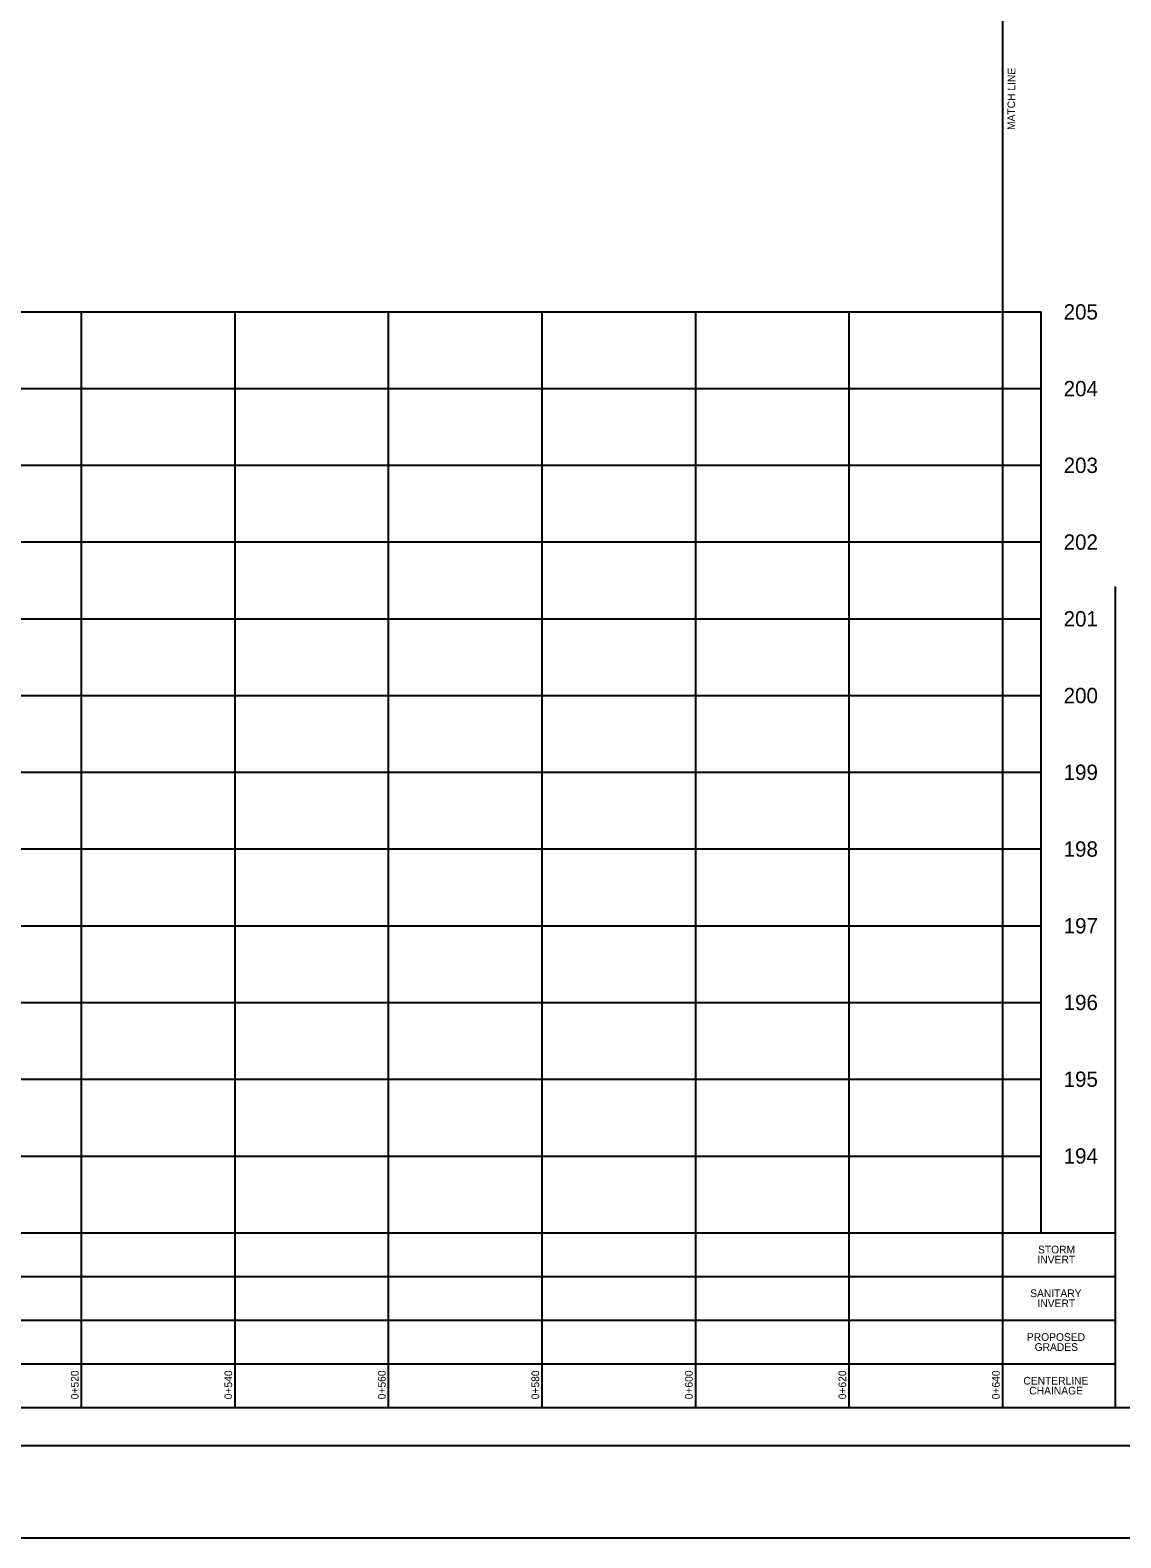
# Model space of a CAD drawing. Extents: x 595568 to 603709, y 4837996 to 4846716.
# Drawn here: x 603142.9 to 603285, y 4846340.6 to 4846537.1 of the extents above; entities that cross this region are included whole.
import ezdxf

# ---------------------------------------------------------------- set-up
doc = ezdxf.new("R2010")
doc.units = 0
for name, color, linetype in [('-PRINT FULLSIZE', 7, 'Continuous'), ('-PRINT HALFSIZE', 7, 'Continuous'), ('ENG_BORDER', 7, 'Continuous'), ('ENG_DIMENSIONS', 7, 'Continuous'), ('ENG_GRID', 7, 'Continuous'), ('ENG_GRIDBORDER', 7, 'Continuous'), ('ENG_TX_DIMENSIONS', 7, 'Continuous'), ('ENG_TX_GRID', 7, 'Continuous')]:
    doc.layers.add(name, color=color, linetype=linetype)

msp = doc.modelspace()

# ---------------------------------------------------------------- linework, layer by layer
at = {"layer": '-PRINT FULLSIZE'}
msp.add_lwpolyline([(602930, 4846340.65), (603377.03, 4846340.65), (603377.03, 4846645.65), (602930, 4846645.65)], close=True, dxfattribs=at)
at = {"layer": '-PRINT HALFSIZE'}
msp.add_lwpolyline([(602959.8, 4846631.64), (603368.72, 4846631.64), (603368.72, 4846352.64), (602959.8, 4846352.64)], close=True, dxfattribs=at)
at = {"layer": 'ENG_BORDER'}
msp.add_line((603284.31, 4846357.64), (603284.31, 4846464.61), dxfattribs=at)
msp.add_lwpolyline([(602975.52, 4846357.64), (603363.72, 4846357.64), (603363.72, 4846626.64), (602975.52, 4846626.64)], close=True, dxfattribs=at)
at = {"layer": 'ENG_DIMENSIONS'}
msp.add_line((603269.61, 4846500.41), (603269.61, 4846626.64), dxfattribs=at)
at = {"layer": 'ENG_GRID'}
for p, q in [((602984.61, 4846500.41), (603274.61, 4846500.41)), ((603149.61, 4846380.41), (603149.61, 4846500.41)), ((603169.61, 4846380.41), (603169.61, 4846500.41)), ((603189.61, 4846380.41), (603189.61, 4846500.41)), ((603209.61, 4846380.41), (603209.61, 4846500.41)), ((603229.61, 4846380.41), (603229.61, 4846500.41)), ((603249.61, 4846380.41), (603249.61, 4846500.41)), ((603269.61, 4846380.41), (603269.61, 4846500.41)), ((602984.61, 4846490.41), (603274.61, 4846490.41)), ((602984.61, 4846480.41), (603274.61, 4846480.41)), ((602984.61, 4846470.41), (603274.61, 4846470.41)), ((602984.61, 4846460.41), (603274.61, 4846460.41)), ((602984.61, 4846450.41), (603274.61, 4846450.41)), ((602984.61, 4846440.41), (603274.61, 4846440.41)), ((602984.61, 4846430.41), (603274.61, 4846430.41)), ((602984.61, 4846420.41), (603274.61, 4846420.41)), ((602984.61, 4846410.41), (603274.61, 4846410.41)), ((602984.61, 4846400.41), (603274.61, 4846400.41)), ((602984.61, 4846390.39), (603274.61, 4846390.39)), ((603149.61, 4846357.64), (603149.61, 4846380.41)), ((603169.61, 4846357.64), (603169.61, 4846380.41)), ((603189.61, 4846357.64), (603189.61, 4846380.41)), ((603209.61, 4846357.64), (603209.61, 4846380.41)), ((603229.61, 4846357.64), (603229.61, 4846380.41)), ((603249.61, 4846357.64), (603249.61, 4846380.41)), ((603269.61, 4846357.64), (603269.61, 4846380.41)), ((602975.52, 4846374.71), (603284.31, 4846374.71)), ((602975.52, 4846369.01), (603284.31, 4846369.01)), ((602975.52, 4846363.31), (603284.31, 4846363.31))]:
    msp.add_line(p, q, dxfattribs=at)
at = {"layer": 'ENG_GRIDBORDER'}
for p, q in [((603274.61, 4846380.41), (603274.61, 4846500.41)), ((602975.52, 4846380.41), (603284.31, 4846380.41))]:
    msp.add_line(p, q, dxfattribs=at)

# ---------------------------------------------------------------- texts
at = {"layer": 'ENG_TX_DIMENSIONS'}
msp.add_text('MATCH LINE', height=1, rotation=89.6422, dxfattribs=at).set_placement((603271.21, 4846524.09))
at = {"layer": 'ENG_TX_GRID'}
for s, height, rotation, p in [('205', 2, 360, (603277.55, 4846499.39)), ('204', 2, 360, (603277.55, 4846489.39)), ('203', 2, 360, (603277.55, 4846479.4)), ('202', 2, 360, (603277.55, 4846469.4)), ('201', 2, 360, (603277.55, 4846459.4)), ('200', 2, 360, (603277.55, 4846449.4)), ('199', 2, 360, (603277.55, 4846439.4)), ('198', 2, 360, (603277.55, 4846429.4)), ('197', 2, 360, (603277.55, 4846419.4)), ('196', 2, 360, (603277.55, 4846409.41)), ('195', 2, 360, (603277.55, 4846399.41)), ('194', 2, 360, (603277.55, 4846389.41)), ('STORM', 1, 360, (603274.21, 4846377.71)), ('INVERT', 1, 360, (603274.14, 4846376.41)), ('SANITARY', 1, 360, (603273.19, 4846372.01)), ('INVERT', 1, 360, (603274.14, 4846370.71)), ('PROPOSED', 1, 360, (603272.76, 4846366.31)), ('GRADES', 1, 360, (603273.77, 4846365.01)), ('0+520', 1, 90, (603149.22, 4846358.7)), ('0+540', 1, 90, (603169.22, 4846358.7)), ('0+560', 1, 90, (603189.22, 4846358.7)), ('0+580', 1, 90, (603209.22, 4846358.7)), ('0+600', 1, 90, (603229.22, 4846358.7)), ('0+620', 1, 90, (603249.22, 4846358.7)), ('0+640', 1, 90, (603269.22, 4846358.7)), ('CENTERLINE', 1, 360, (603272.3, 4846360.62)), ('CHAINAGE', 1, 360, (603273.07, 4846359.33))]:
    msp.add_text(s, height=height, rotation=rotation, dxfattribs=at).set_placement(p)

doc.saveas('drawing.dxf')
